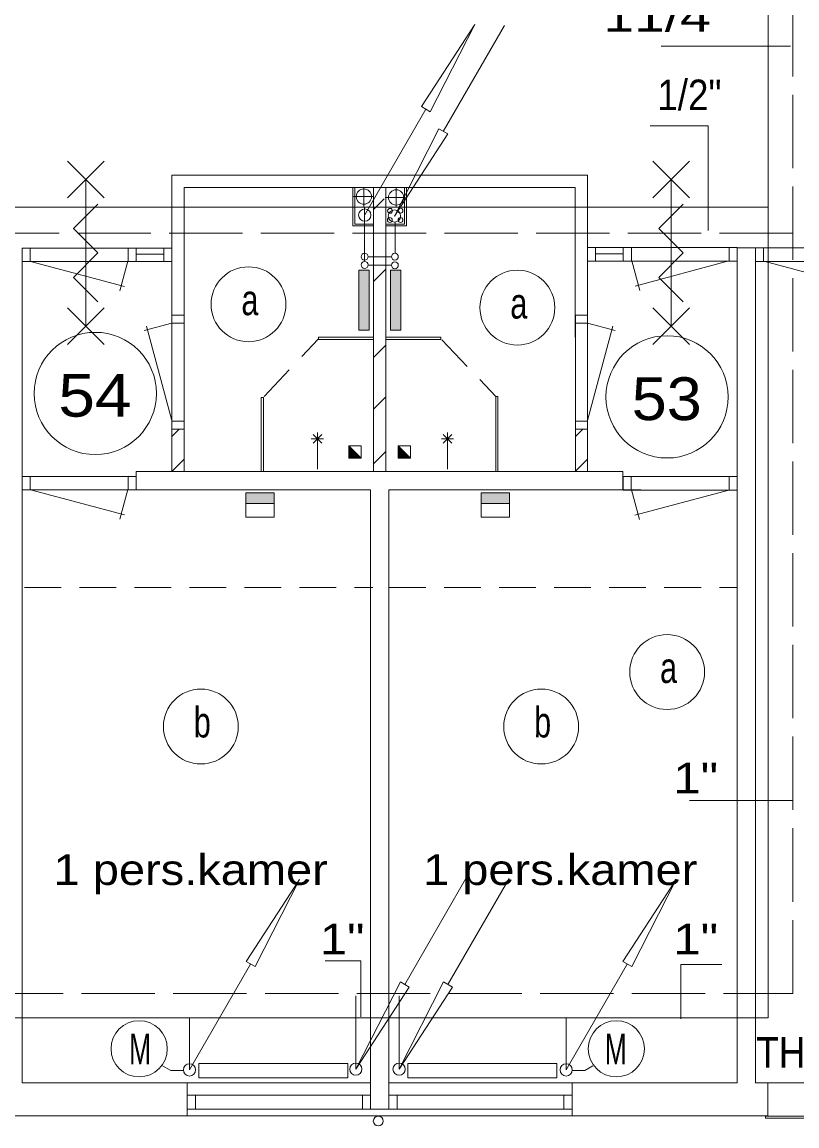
# Model space of a CAD drawing. Extents: x 295824 to 414724, y 24924 to 109024.
# Drawn here: x 320090 to 326428, y 30581 to 39611 of the extents above; entities that cross this region are included whole.
import ezdxf
from ezdxf.enums import TextEntityAlignment as Align

# ---------------------------------------------------------------- set-up
doc = ezdxf.new("R2010")
doc.units = 0
doc.header["$LTSCALE"] = 100
for name, pattern in [('DOT_DASHED', [7.7, 5, -1.2, 0.3, -1.2]), ('LONG_DASHED', [7.5, 6, -1.5]), ('MEDIUM_DASHED', [4.5, 3, -1.5])]:
    doc.linetypes.add(name, pattern=pattern)
doc.layers.add('16', color=7, linetype='Continuous', lineweight=13)
doc.layers.add('61', color=7, linetype='Continuous', lineweight=13)

msp = doc.modelspace()

# ---------------------------------------------------------------- hatches: boundary and pattern name
at = {"layer": '16'}
for points in [[(322843.9, 37090.3), (322929.4, 37090.3), (322929.4, 37582.5), (322843.9, 37582.5)], [(323103.1, 37090.3), (323188.5, 37090.3), (323188.5, 37582.5), (323103.1, 37582.5)], [(322152.7, 35760.1), (321921.2, 35760.1), (321921.2, 35673.6), (322152.7, 35673.6)], [(324077.6, 35760.1), (323846.1, 35760.1), (323846.1, 35673.6), (324077.6, 35673.6)]]:
    msp.add_hatch(color=256, dxfattribs=at).paths.add_polyline_path(points)
at = {"layer": '61'}
for points in [[(322763.2, 36143.3), (322863.2, 36043.3), (322763.2, 36043.3)], [(323166.3, 36143.3), (323266.3, 36043.3), (323166.3, 36043.3)]]:
    msp.add_hatch(color=256, dxfattribs=at).paths.add_polyline_path(points)

# ---------------------------------------------------------------- linework, layer by layer
at = {"layer": '16'}
for p, q in [((326194, 31465.3), (326194, 46658)), ((324035.7, 39583.4), (323535.7, 38717.4)), ((326374.6, 39414.5), (325318.6, 39414.5)), ((322892.7, 38033), (323392.7, 38899)), ((326194, 38096.3), (310885.9, 38096.3)), ((322891.2, 38096.3), (322891.2, 37656.7)), ((323111.5, 37621.3), (322919.8, 37621.3)), ((321921.2, 35673.6), (321921.2, 35559.7)), ((323846.1, 35673.6), (323846.1, 35559.7)), ((326389.9, 33243.2), (325548.2, 33243.2)), ((323720.3, 32603.9), (323220.3, 31737.9)), ((324073.8, 32603.9), (323573.8, 31737.9)), ((321459.6, 31039), (321959.6, 31905)), ((324540.4, 31039), (325040.4, 31905)), ((309466.3, 31465.3), (325376.7, 31465.3)), ((321459.6, 31038.7), (321459.6, 31465.3)), ((324540.4, 31039), (324540.4, 31465.3))]:
    msp.add_line(p, q, dxfattribs=at)
at = {"layer": '16', "linetype": 'LONG_DASHED'}
for p, q in [((326394, 31665.3), (326394, 46458)), ((323142.4, 37972.8), (323142.4, 37717.8)), ((326394, 37884.5), (311137.1, 37884.5)), ((322919.9, 37692.1), (323111.4, 37692.1)), ((310827, 31665.3), (326394, 31665.3)), ((322820.3, 31044.9), (322820.3, 31665.3)), ((323173.8, 31045.2), (323173.8, 31665.3))]:
    msp.add_line(p, q, dxfattribs=at)
at = {"layer": '16'}
for points in [[(323792.7, 39592), (323428.7, 38878), (323356.7, 38920)], [(323135.7, 38024.4), (323499.7, 38738.4), (323571.7, 38696.4)], [(322843.9, 37090.3), (322929.4, 37090.3), (322929.4, 37582.5), (322843.9, 37582.5)], [(323103.1, 37090.3), (323188.5, 37090.3), (323188.5, 37582.5), (323103.1, 37582.5)], [(322152.7, 35760.1), (321921.2, 35760.1), (321921.2, 35673.6), (322152.7, 35673.6)], [(324077.6, 35760.1), (323846.1, 35760.1), (323846.1, 35673.6), (324077.6, 35673.6)], [(322359.6, 32598), (321995.6, 31884), (321923.6, 31926)], [(325440.4, 32598), (325076.4, 31884), (325004.4, 31926)], [(322820.3, 31044.9), (323184.3, 31758.9), (323256.3, 31716.9)], [(323173.8, 31044.9), (323537.8, 31758.9), (323609.8, 31716.9)], [(321536.2, 31092), (322755.5, 31092), (322755.5, 30974.1), (321536.2, 30974.1)], [(323244.5, 31092), (324463.8, 31092), (324463.8, 30974.1), (323244.5, 30974.1)]]:
    msp.add_lwpolyline(points, close=True, dxfattribs=at)
for points in [[(325701.2, 37906), (325701.2, 38763.6), (325226.8, 38763.6)], [(322152.7, 35673.6), (322152.7, 35559.7), (321921.2, 35559.7)], [(324077.6, 35673.6), (324077.6, 35559.7), (323846.1, 35559.7)], [(322860.3, 31472.7), (322860.3, 31932.1), (322569.6, 31932.1)], [(325477.4, 31457.4), (325477.4, 31901.5), (325814.1, 31901.5)], [(309466.3, 31039), (309466.3, 31465.3), (326194, 31465.3)], [(321408.1, 31033.7), (321305.6, 31033.7), (321239.1, 31072.1)], [(324590.2, 31033.7), (324692.7, 31033.7), (324759.2, 31072.1)]]:
    msp.add_lwpolyline(points, dxfattribs=at)
for centre, radius in [((322892.7, 38032.7), 50), ((323135.7, 38024.7), 50), ((322892, 37692.1), 27.9), ((323139.4, 37692.1), 27.9), ((322892, 37624.3), 27.9), ((323139.4, 37621.3), 27.9), ((321047.6, 31211.8), 229.9), ((324950.7, 31211.8), 229.9), ((321459.6, 31038.7), 50), ((322820.3, 31045.2), 50), ((323173.8, 31045.2), 50), ((324540.4, 31038.7), 50)]:
    msp.add_circle(centre, radius, dxfattribs=at)
at = {"layer": '61'}
for p, q in [((320760.7, 38472.2), (320460.7, 38172.2)), ((320460.7, 38472.2), (320760.7, 38172.2)), ((325548.4, 38472.2), (325248.4, 38172.2)), ((325248.4, 38472.2), (325548.4, 38172.2)), ((320610.7, 37122.2), (320610.7, 38322.2)), ((325398.4, 37122.2), (325398.4, 38322.2)), ((321415.3, 37214.4), (321415.3, 38259)), ((322795.5, 38259), (322795.5, 37944)), ((322810.5, 38259), (322810.5, 37959)), ((322965.3, 35934), (322965.3, 38259)), ((323065.3, 35934), (323065.3, 38259)), ((323218.9, 38259), (323218.9, 37959)), ((323233.2, 38259), (323233.2, 37944)), ((323051.7, 38165.1), (322966.4, 38079.8)), ((322965.1, 37944), (322795.5, 37944)), ((322964.7, 37959), (322810.5, 37959)), ((323218.9, 37959), (323065.3, 37959)), ((323233.2, 37944), (323065.3, 37944)), ((324715.3, 37216.6), (324715.3, 38003.7)), ((320156.8, 37763.1), (320156.8, 37653.1)), ((320956.8, 37763.1), (320956.8, 37653.1)), ((321023.8, 37763.1), (321023.8, 37653.1)), ((321249.3, 37763.1), (321249.3, 37653.1)), ((324781.7, 37767), (324781.7, 37657)), ((325007.2, 37767), (325007.2, 37657)), ((325074.2, 37767), (325074.2, 37657)), ((325874.2, 37767), (325874.2, 37657)), ((325940.1, 37765.6), (325940.1, 30933.6)), ((325940.1, 37765.6), (326090.1, 37765.6)), ((326090.1, 37765.6), (326090.1, 30933.6)), ((326154.7, 37764.6), (326154.7, 37654.6)), ((320090.1, 37658.6), (320090.1, 30933.6)), ((321024.6, 37712.3), (321249.3, 37712.3)), ((321315.3, 37214.4), (321315.3, 37659)), ((325006.4, 37716.2), (324781.7, 37716.2)), ((325077, 37659), (325142, 37416.2)), ((320159.4, 37652.9), (320926.7, 37447.3)), ((320954, 37655.1), (320888.9, 37412.4)), ((323064.9, 37589), (322966.4, 37490.5)), ((325871.6, 37656.8), (325104.3, 37451.2)), ((326157.3, 37654.4), (326924.6, 37448.8)), ((324615.3, 37553.7), (324615.3, 37216.6)), ((320760.7, 37272.2), (320460.7, 36972.2)), ((320460.7, 37272.2), (320760.7, 36972.2)), ((321315.3, 37215.2), (321315.3, 36280.4)), ((321415.3, 37214.4), (321315.3, 37214.4)), ((321415.3, 36280.4), (321415.3, 37214.4)), ((324615.5, 36280), (324615.5, 37214)), ((324615.5, 37214), (324715.5, 37214)), ((324715.5, 37214), (324715.5, 36280)), ((325548.4, 37272.2), (325248.4, 36972.2)), ((325248.4, 37272.2), (325548.4, 36972.2)), ((321315.6, 37148.4), (321088.3, 37087.5)), ((321315.6, 36351), (321108.7, 37123.2)), ((321415.2, 37147.4), (321315.9, 37147.4)), ((324615.6, 37147), (324714.9, 37147)), ((324715.2, 37148), (324942.5, 37087.1)), ((324715.2, 36350.6), (324922.1, 37122.8)), ((322514.3, 37033.2), (322964.4, 37033.2)), ((322514.3, 37015.2), (322514.3, 37033.2)), ((323065.7, 37033.2), (323516, 37033.2)), ((322514.3, 37015.2), (322964.4, 37015.2)), ((323064.9, 36969), (322966.4, 36870.5)), ((321315.2, 36613.5), (321315.2, 36723.9)), ((322046.8, 36541.2), (322046.8, 35936.4)), ((322064.8, 36541.2), (322046.8, 36541.2)), ((322064.8, 36541.2), (322064.8, 35936.4)), ((323064.9, 36546.5), (322966.4, 36448)), ((323964.6, 36547.3), (323964.6, 35938.9)), ((323982.6, 36547.3), (323964.6, 36547.3)), ((323982.6, 36547.3), (323982.6, 35938.9)), ((321415.5, 36347.4), (321315.3, 36347.4)), ((324615.3, 36347), (324715.5, 36347)), ((321371, 36278.7), (321314.3, 36222)), ((321414.9, 36280.4), (321314.8, 36280.4)), ((321315.1, 36280.4), (321315.1, 35934)), ((321414.9, 36280), (321414.9, 35933.6)), ((322469.9, 36167.4), (322540.6, 36238.1)), ((322469.9, 36238.1), (322540.6, 36167.4)), ((322505.2, 36152.8), (322505.2, 36252.8)), ((323534.3, 36167.4), (323605, 36238.1)), ((323534.3, 36238.1), (323605, 36167.4)), ((323569.7, 36152.8), (323569.7, 36252.8)), ((324615.5, 36280), (324715.5, 36280)), ((324672.9, 36278.7), (324616.2, 36222)), ((324616.5, 36280.4), (324616.5, 35934)), ((324715.2, 36280.4), (324715.2, 35934)), ((322455.2, 36202.8), (322555.2, 36202.8)), ((322505.2, 36152.8), (322505.2, 35952.8)), ((323519.7, 36202.8), (323619.7, 36202.8)), ((323569.7, 36152.8), (323569.7, 35952.8)), ((321414.7, 36034.7), (321314.3, 35934.3)), ((323064.9, 36098.9), (322966.4, 36000.4)), ((324715.2, 36034.7), (324614.8, 35934.3)), ((320090.9, 35894.5), (320090.9, 35784.1)), ((321021.7, 35894.5), (320090.9, 35894.5)), ((320156.8, 35894.8), (320156.8, 35784.8)), ((320956.8, 35894.8), (320956.8, 35784.8)), ((321023.8, 35894.8), (321023.8, 35784.8)), ((325005, 35934), (321414.9, 35934)), ((325005.9, 35892.8), (325005.9, 35782.8)), ((325008.1, 35892.5), (325938.8, 35892.5)), ((325072.9, 35892.8), (325072.9, 35782.8)), ((325872.9, 35892.8), (325872.9, 35782.8)), ((322940.3, 35784), (320091, 35784)), ((320159.4, 35784.7), (320926.7, 35579.1)), ((320954, 35786.8), (320888.9, 35544.1)), ((322940.3, 35784), (320997.9, 35784)), ((323090.3, 35784), (325150.3, 35784)), ((325075.8, 35784.8), (325140.8, 35542.1)), ((325870.4, 35782.7), (325103.1, 35577.1)), ((321441, 30932), (321441, 30662)), ((322941, 30932), (322941, 30717.3)), ((323090, 30932), (323090, 30717.3)), ((324590, 30932), (324590, 30662)), ((328940.1, 30933.6), (326090.1, 30933.6)), ((326190.3, 30663.6), (326190.3, 30932.5)), ((321441.2, 30830.3), (321441.2, 30717.3)), ((322940.2, 30831.3), (321442.1, 30831.3)), ((321508.2, 30830.8), (321508.2, 30717.9)), ((322873.2, 30831.3), (322873.2, 30717.9)), ((322940.2, 30831.3), (322940.2, 30717.3)), ((323090.2, 30830.3), (323090.2, 30717.3)), ((324589.2, 30831.3), (323091.1, 30831.3)), ((323157.2, 30830.8), (323157.2, 30717.3)), ((324522.2, 30831.3), (324522.2, 30717.9)), ((324589.2, 30831.3), (324589.2, 30717.3)), ((323157.2, 30717.3), (321441.2, 30717.3)), ((324589.2, 30717.3), (323090.2, 30717.3)), ((326190, 30663.6), (307806, 30663.6)), ((326171.2, 30661.4), (326564.4, 30661.4)), ((326171.2, 30643.9), (326171.2, 30661.4)), ((326171.2, 30643.9), (326564.4, 30643.9))]:
    msp.add_line(p, q, dxfattribs=at)
at = {"layer": '61', "linetype": 'DOT_DASHED'}
for p, q in [((322886.5, 38258.4), (322886.5, 38099.1)), ((323149.7, 38257.1), (323149.7, 38093)), ((322801.4, 38184.2), (322965.5, 38184.2)), ((323061.2, 38176.8), (323225.2, 38176.8))]:
    msp.add_line(p, q, dxfattribs=at)
at = {"layer": '61', "linetype": 'MEDIUM_DASHED'}
for p, q in [((322069.1, 36548.8), (322513.1, 37016.1)), ((323523.4, 37012.1), (323965.2, 36547.1)), ((320109.5, 34984.3), (322959.5, 34984.3)), ((323093.5, 34984.3), (325940.1, 34984.3))]:
    msp.add_line(p, q, dxfattribs=at)
at = {"layer": '61'}
for points in [[(324715.3, 37759), (324715.3, 38359), (321315.3, 38359), (321315.3, 37759)], [(322940.5, 38259), (321415.3, 38259), (321415.3, 37309)], [(324615.3, 37033.2), (324615.3, 38259), (322735.3, 38259)], [(320710.7, 37322.2), (320510.7, 37522.2), (320710.7, 37722.2), (320510.7, 37922.2), (320710.7, 38122.2)], [(325498.4, 37322.2), (325298.4, 37522.2), (325498.4, 37722.2), (325298.4, 37922.2), (325498.4, 38122.2)], [(323065.7, 37015.2), (323516, 37015.2), (323516, 37033.2)], [(322863.2, 36043.3), (322763.2, 36043.3), (322763.2, 36143.3)], [(323266.3, 36043.3), (323166.3, 36043.3), (323166.3, 36143.3)], [(321024.3, 35784.1), (321024.3, 35934), (321429.7, 35934)], [(323090.3, 35784), (325005, 35784), (325005, 35934)], [(325938.8, 35892.5), (325938.8, 35782.1), (325005.5, 35782.1)], [(320090.1, 30933.6), (322940.1, 30933.6), (322940.1, 35783.6)], [(325940.1, 30933.6), (323090.1, 30933.6), (323090.1, 35783.6)]]:
    msp.add_lwpolyline(points, dxfattribs=at)
for points in [[(320090.9, 37762.8), (320090.9, 37652.4), (321315.2, 37652.4), (321315.2, 37762.8)], [(325940.1, 37766.6), (325940.1, 37656.3), (324715.8, 37656.3), (324715.8, 37766.6)], [(326088.8, 37764.3), (326088.8, 37653.9), (327313.1, 37653.9), (327313.1, 37764.3)], [(322863.2, 36043.3), (322863.2, 36143.3), (322763.2, 36143.3)], [(322763.2, 36143.3), (322863.2, 36043.3), (322763.2, 36043.3)], [(323266.3, 36043.3), (323266.3, 36143.3), (323166.3, 36143.3)], [(323166.3, 36143.3), (323266.3, 36043.3), (323166.3, 36043.3)]]:
    msp.add_lwpolyline(points, close=True, dxfattribs=at)
for centre, radius in [((322885.9, 38183.5), 62.5), ((323149.7, 38176.7), 62.5), ((323100.1, 38066.8), 20), ((323184.8, 38068.2), 20), ((323098, 37991.7), 20), ((323185.5, 37991.7), 20), ((321942, 37302.8), 306.3), ((324141.4, 37275), 306.3), ((320688.9, 36573), 500), ((325366.2, 36545.1), 500), ((325366.4, 34293.8), 306.3), ((321552.2, 33848), 306.3), ((324336.3, 33848), 306.3), ((323003.1, 30620.7), 40)]:
    msp.add_circle(centre, radius, dxfattribs=at)

# ---------------------------------------------------------------- texts
at = {"layer": '16'}
for s, width, p in [(' 11/4"', 1.35, (324719.8, 39533.9)), ('1/2"', 0.9, (325286.1, 38890.7)), ('1"', 1.2, (325417.7, 33302)), ('1"', 1.2, (322525.2, 31984.8)), ('1"', 1.2, (325417.7, 31984.8)), ('M', 0.65, (320965.3, 31085.1)), ('M', 0.65, (324855.8, 31085.1)), ('TH', 0.9, (326096, 31056.9))]:
    msp.add_text(s, height=250, dxfattribs=dict(at, width=width)).set_placement(p)
at = {"layer": '61'}
for s, width, p in [('a', 0.75, (321884, 37213.7)), ('a', 0.75, (324083.4, 37185.8)), ('a', 0.75, (325308.4, 34204.6)), ('b', 0.75, (321494.2, 33758.9)), ('b', 0.75, (324278.3, 33758.9)), ('1 pers.kamer', 1.15, (320347.6, 32552.1)), ('1 pers.kamer', 1.15, (323369.8, 32552.1))]:
    msp.add_text(s, height=250, dxfattribs=dict(at, width=width)).set_placement(p)
for s, width, p in [('54', 1.15, (320686, 36383.1)), ('53', 1.1, (325363.3, 36355.2))]:
    msp.add_text(s, height=350, dxfattribs=dict(at, width=width)).set_placement(p, align=Align.CENTER)

doc.saveas('drawing.dxf')
